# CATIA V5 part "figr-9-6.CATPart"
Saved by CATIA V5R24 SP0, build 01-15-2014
Part number: Part2
Bounding box of the stored display mesh (mm): x -75 to 75, y -75 to 96.278, z -26.878 to 0
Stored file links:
  D:\KAVITA\CATIA V5-6R2014 Project_ Kavita\CATIA V5-6R2014_partfiles\Partfiles\c09_catia_v5-6r2014_prt\figr-9-6.CATPart
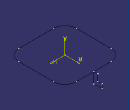
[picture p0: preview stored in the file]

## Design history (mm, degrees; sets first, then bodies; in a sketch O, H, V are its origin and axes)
Body1 (main body)
  Sketch1 on xy-plane, origin (0, 0, 0), H (1, 0, 0), V (0, 1, 0)
    point P1 (-75, 75)
    line L1 (-45, 75) -> (45, 75)
    line L2 (75, 45) -> (75, -45)
    line L3 (45, -75) -> (-45, -75)
    line L4 (-75, -45) -> (-75, 45)
    point P2 (75, 75)
    point P3 (75, -75)
    point P4 (-75, -75)
    axis line L5 (75, -75) -> (-75, 75)
    arc A1 centre (45, -45) radius 30 from (75, -45) to (45, -75) cw
    arc A2 centre (45, 45) radius 30 from (45, 75) to (75, 45) cw
    arc A3 centre (-45, 45) radius 30 from (-45, 75) to (-75, 45) ccw
    arc A4 centre (-45, -45) radius 30 from (-45, -75) to (-75, -45) cw
    distance P2 P3 = 150
    distance P3 P4 = 150
    radius A1 = 30
    radius A2 = 30
    radius A3 = 30
    radius A4 = 30
    horizontal: L1 H, L3 H
    vertical: L2 V, L4 V
    midpoint: O L5
    coincidence: L2 P3, L3 P3, L1 P2, L2 P2, L1 P1, L4 P1, L3 P4, L4 P4
    tangency: A1 L2, A1 L3, A2 L1, A2 L2, A3 L1, A3 L4, A4 L3, A4 L4
  Sketch2 on yz-plane, origin (0, 0, 0), H (0, 1, 0), V (0, 0, 1)
    point P1 (85, 0)
    line L1 (85, 0) -> (85, -16.8782)
    line L2 (85, -16.8782) -> (96.2781, -16.8782)
    line L3 (96.2781, -16.8782) -> (96.2781, -26.8782)
    line L4 (96.2781, -26.8782) -> (75, -26.8782)
    line L5 (75, -26.8782) -> (75, 0)
    point P6 (75, 0)
    line L6 (75, 0) -> (85, 0)
    reference projected point E1 (75, 0) from edge of Sketch1
    length L3 = 10
    length L6 = 10
    coincidence: P1 H, P6 H, P6 E1
    vertical: L1 V, L3 V, L5 V
    horizontal: L2 H, L4 H, L6 H
  Rib1: profile Sketch2, centre curve Sketch1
